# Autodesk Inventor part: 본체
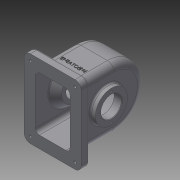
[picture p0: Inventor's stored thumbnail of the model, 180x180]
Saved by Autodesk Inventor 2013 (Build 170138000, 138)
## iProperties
Created: 2016-10
Part Number: 본체
Material: Generic
Document SubType Name: Modeling
Designer: Administrator
Density: 1 g/cm^3
Author: Administrator
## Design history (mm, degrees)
sketch "스케치1"
  geometry: L1 (0, -58)-(-80, -58); L2 (-80, -58)-(-80, 58); L3 (-80, 58)-(0, 58); L4 (0, 58)-(0, -58); L5 (0, -58)-(58, -58); L6 (58, -58)-(58, 58); L7 (58, 58)-(0, 58); L8 (0, 58)-(0, -58); 2 further points
  constraints: 16 end point, 4 parallel, 2 horizontal, 2 perpendicular, 1 coincident, 1 midpoint
  dimensions: "d0" = 116 distance of L3.end L1.start; "d2" = 80 distance of L2.end L3.end; "d3" = 116 distance of L5.end L6.end; "d4" = 58 distance of L6.end L7.end
extrude "돌출1" new body sketch "스케치1" stored distance "d5" = 77; taper "d6" = 0 deg
fillet "모깎기1" dims "d7" = 58
sketch "스케치2"
  geometry: L1 (-38.5, -80)-(-38.5, 58) reference; L2 (-38.5, 58)-(38.5, 58) reference; L3 (38.5, 58)-(38.5, -80) reference; L4 (38.5, -80)-(-38.5, -80) reference; L5 (-33.5, 52)-(33.5, 52); L6 (33.5, 52)-(33.5, 0); L7 (33.5, 0)-(-33.5, 0); L8 (-33.5, 0)-(-33.5, 52); 2 further points
  constraints: 8 end point, 2 parallel, 1 coincident, 1 horizontal, 1 midpoint, 1 perpendicular
  dimensions: "d8" = 5 distance between parallel lines of L1 L8; "d9" = 52 distance between parallel lines of L7 L5
revolve "회전1" sketch "스케치2" stored, may be unused: angle "d10" = 90 deg
sketch "스케치3"
  geometry: L1 (-38.5, -80)-(-38.5, 58) reference; L2 (-38.5, 58)-(38.5, 58) reference; L3 (38.5, 58)-(38.5, -80) reference; L4 (38.5, -80)-(-38.5, -80) reference; L5 (33.5, -52)-(33.5, 52) reference; L6 (33.5, 52)-(-33.5, 52) reference; L7 (-33.5, 52)-(-33.5, -52) reference; L8 (-33.5, -52)-(33.5, -52) reference; L9 (-33.5, 0)-(33.5, 0); L10 (33.5, 0)-(33.5, -80); L11 (33.5, -80)-(-33.5, -80); L12 (-33.5, -80)-(-33.5, 0); 1 further point
  constraints: 8 end point, 2 parallel, 1 horizontal, 1 midpoint, 1 perpendicular, 1 point on line
  dimensions: "d11" = 5 distance between parallel lines of L3 L10
extrude "돌출2" cut sketch "스케치3" stored distance "d12" = 104; taper "d13" = 0 deg
sketch "스케치4"
  geometry: L1 (72, 6)-(5, 6) reference; L2 (5, 6)-(5, 110) reference; L3 (5, 110)-(72, 110) reference; L4 (72, 110)-(72, 6) reference; L5 (93.5, 133)-(-16.5, 133); L6 (-16.5, 133)-(-16.5, -17); L7 (-16.5, -17)-(93.5, -17); L8 (93.5, -17)-(93.5, 133); L9 (93.5, 133)-(-16.5, -17); L10 (-16.5, 133)-(93.5, -17); 1 further point
  constraints: 12 end point, 2 midpoint, 2 parallel, 1 horizontal, 1 perpendicular
  dimensions: "d14" = 110 distance of L6.end L7.end; "d16" = 150 distance of L7.end L5.start
extrude "돌출3" join sketch "스케치4" distance "d17" = 15; taper "d18" = 0 deg
sketch "스케치5"
  geometry: L1 (-33.5, 52)-(-33.5, -80) reference; L2 (-33.5, -80)-(-55, -80) reference; L3 (-55, -80)-(-55, -65) reference; L4 (-55, -65)-(-38.5, -65) reference; L5 (-38.5, -65)-(-38.5, 58) reference; L6 (-38.5, 58)-(38.5, 58) reference; L7 (38.5, 58)-(38.5, -65) reference; L8 (38.5, -65)-(55, -65) reference; L9 (55, -65)-(55, -80) reference; L10 (55, -80)-(33.5, -80) reference; L11 (33.5, -80)-(33.5, 52) reference; L12 (33.5, 52)-(-33.5, 52) reference; L13 (37.5, -15)-(48.5, -15); L14 (48.5, -15)-(48.5, 16); L15 (48.5, 16)-(37.5, 16); L16 (37.5, 16)-(37.5, -15); L17 (33.5, -15)-(38.5, -15); 1 further point
  constraints: 10 end point, 3 point on line, 2 parallel, 2 perpendicular, 1 horizontal
  dimensions: "d20" = 87 distance between parallel lines of L5 L14; "d21" = 31 distance of L13.end L14.end; "d22" = 11 distance of L14.end L15.end; "d23" = 65 distance between parallel lines of L10 L13
revolve "회전2" sketch "스케치5" stored, may be unused: angle "d24" = 90 deg
sketch "스케치6"
  geometry: L1 (-33.5, 52)-(-33.5, -80) reference; L2 (-33.5, -80)-(-55, -80) reference; L3 (-55, -80)-(-55, -65) reference; L4 (-55, -65)-(-38.5, -65) reference; L5 (-38.5, -65)-(-38.5, 58) reference; L6 (-38.5, 58)-(38.5, 58) reference; L7 (38.5, 58)-(38.5, 16) reference; L8 (38.5, 16)-(48.5, 16) reference; L9 (48.5, 16)-(48.5, -46) reference; L10 (48.5, -46)-(38.5, -46) reference; L11 (38.5, -46)-(38.5, -65) reference; L12 (38.5, -65)-(55, -65) reference; L13 (55, -65)-(55, -80) reference; L14 (55, -80)-(33.5, -80) reference; L15 (33.5, -80)-(33.5, 52) reference; L16 (33.5, 52)-(-33.5, 52) reference; L17 (-43.5, 22.5)-(-36.5, 22.5); L18 (-36.5, 22.5)-(-36.5, -15); L19 (-36.5, -15)-(-43.5, -15); L20 (-43.5, -15)-(-43.5, 22.5); 1 further point
  constraints: 8 end point, 2 parallel, 1 horizontal, 1 perpendicular
  dimensions: "d25" = 65 distance between parallel lines of L2 L19; "d26" = 37.5 distance of L19.end L17.start; "d27" = 5 distance between parallel lines of L5 L20; "d28" = 7 distance of L17.start L17.end
revolve "회전3" sketch "스케치6" stored, may be unused: angle "d29" = 90 deg
sketch "스케치7"
  geometry: L1 (-33.5, 52)-(-33.5, -80) reference; L2 (-33.5, -80)-(-55, -80) reference; L3 (-55, -80)-(-55, -65) reference; L4 (-55, -65)-(-38.5, -65) reference; L5 (-38.5, -65)-(-38.5, -52.5) reference; L6 (-38.5, -52.5)-(-43.5, -52.5) reference; L7 (-43.5, -52.5)-(-43.5, 22.5) reference; L8 (-43.5, 22.5)-(-38.5, 22.5) reference; L9 (-38.5, 22.5)-(-38.5, 58) reference; L10 (-38.5, 58)-(38.5, 58) reference; L11 (38.5, 58)-(38.5, 16) reference; L12 (38.5, 16)-(48.5, 16) reference; L13 (48.5, 16)-(48.5, -46) reference; L14 (48.5, -46)-(38.5, -46) reference; L15 (38.5, -46)-(38.5, -65) reference; L16 (38.5, -65)-(55, -65) reference; L17 (55, -65)-(55, -80) reference; L18 (55, -80)-(33.5, -80) reference; L19 (33.5, -80)-(33.5, 52) reference; L20 (33.5, 52)-(-33.5, 52) reference; L21 (-43.5, -15)-(48.5, -15); L22 (-33.5, 13)-(-19.5, 13); L23 (-19.5, 13)-(-19.5, -15); L24 (-19.5, 13)-(-33.5, 24.747); L25 (-33.5, 24.747)-(-33.5, -15); L26 (-33.5, -15)-(-19.5, -15); 1 further point
  constraints: 12 end point, 5 point on line, 2 midpoint, 2 parallel
  dimensions: "d31" = 65 distance between parallel lines of L2 L21; "d32" = 28 distance between parallel lines of L21 L22; "d34" = 50 deg angle of L23 L24; "d35" = 24 distance between parallel lines of L7 L23
revolve "회전4" sketch "스케치7" stored, may be unused: angle "d36" = 90 deg
sketch "스케치8"
  geometry: C1 r 31 at (0, 0) reference; C2 r 20 at (0, 0); 1 further point
  constraints: 1 centre point, 1 coincident
  dimensions: "d37" = 40 diameter of C2
extrude "돌출4" cut sketch "스케치8" stored distance "d38" = 15; taper "d39" = 0 deg
chamfer "모따기1" distance "d40" = 1; stored, may be unused: second distance "d41" = 2, angle "d42" = 45 deg
sketch "스케치9"
  geometry: L1 (48.5, 6)-(47.5, 5) reference; L2 (47.5, 5)-(33.5, 5) reference; L3 (33.5, 5)-(33.5, 52) reference; L4 (33.5, 52)-(-33.5, 52) reference; L5 (-33.5, 52)-(-33.5, 24.747) reference; L6 (-33.5, 24.747)-(-19.5, 13) reference; L7 (-19.5, 13)-(-19.5, 5) reference; L8 (-19.5, 5)-(-42.5, 5) reference; L9 (-42.5, 5)-(-43.5, 6) reference; L10 (-43.5, 6)-(-43.5, 22.5) reference; L11 (-43.5, 22.5)-(-38.5, 22.5) reference; L12 (-38.5, 22.5)-(-38.5, 58) reference; L13 (-38.5, 58)-(38.5, 58) reference; L14 (38.5, 58)-(38.5, 16) reference; L15 (38.5, 16)-(48.5, 16) reference; L16 (48.5, 16)-(48.5, 6) reference; L17 (-55, -65)-(-38.5, -65) reference; L18 (-38.5, -65)-(-38.5, -52.5) reference; L19 (-38.5, -52.5)-(-43.5, -52.5) reference; L20 (-43.5, -52.5)-(-43.5, -36) reference; L21 (-43.5, -36)-(-42.5, -35) reference; L22 (-42.5, -35)-(-19.5, -35) reference; L23 (-19.5, -35)-(-19.5, -43) reference; L24 (-19.5, -43)-(-33.5, -54.747) reference; L25 (-33.5, -54.747)-(-33.5, -80) reference; L26 (-33.5, -80)-(-55, -80) reference; L27 (-55, -80)-(-55, -65) reference; L28 (38.5, -65)-(55, -65) reference; L29 (55, -65)-(55, -80) reference; L30 (55, -80)-(33.5, -80) reference; L31 (33.5, -80)-(33.5, -35) reference; L32 (33.5, -35)-(47.5, -35) reference; L33 (47.5, -35)-(48.5, -36) reference; L34 (48.5, -36)-(48.5, -46) reference; L35 (48.5, -46)-(38.5, -46) reference; L36 (38.5, -46)-(38.5, -65) reference; L37 (-6, 64)-(0, 64); L38 (0, 64)-(0, 55); L39 (-6, 55)-(-6, 64); L40 (-7.587, 55)-(0, 55); L41 (-6, 64)-(-7.587, 55); 1 further point
  constraints: 10 end point, 2 perpendicular, 1 horizontal, 1 parallel, 1 point on line
  dimensions: "d43" = 33.5 distance between parallel lines of L5 L38; "d44" = 144 distance between parallel lines of L26 L37; "d45" = 6 distance of L37.start L37.end; "d46" = 100 deg angle of L13 L41; "d47" = 9 distance between parallel lines of L37 L40
revolve "회전5" sketch "스케치9" stored, may be unused: angle "d48" = 90 deg
sketch "스케치10" dims "d49" = 58
  geometry: C1 r 21 at (0, 0) reference; 3 further points
  constraints: 1 coincident, 1 vertical alignment, 2 other
  dimensions: "d72" = 14 distance of point (0, 15) point (0, 29)
hole "구멍1" sketch "스케치10" at (0, 29) diameter "d50" = 2.459; stored, may be unused: countersink angle "d54" = 90 deg, drill point angle "d56" = 118 deg; dims "d51" = 6, "d52" = 4, "d53" = 2, "d55" = 8
sketch "스케치11" dims "d60" = 52
  geometry: C1 r 21 at (0, 0) reference; 3 further points
  constraints: 1 coincident, 1 vertical alignment, 2 other
  dimensions: "d61" = 11 distance of point (0, 15) point (0, 26)
hole "구멍2" sketch "스케치11" at (0, 26) diameter "d62" = 2.459; stored, may be unused: countersink angle "d66" = 90 deg, drill point angle "d68" = 118 deg; dims "d63" = 6, "d64" = 4, "d65" = 2, "d67" = 8
fillet "모깎기2" dims "d73" = 13
fillet "모깎기3" dims "d74" = 8
fillet "모깎기4" dims "d75" = 12
sketch "스케치12"
  geometry: C1 r 6 at (0, 0) reference; 1 further point
  constraints: 1 coincident
hole "구멍3" sketch "스케치12" at (0, 0) diameter "d76" = 4.459; stored, may be unused: countersink angle "d80" = 90 deg, drill point angle "d82" = 118 deg; dims "d77" = 6, "d78" = 4, "d79" = 2, "d81" = 15
sketch "스케치13"
  geometry: C1 r 6 at (-4.5, 5); C2 r 6 at (81.5, 5); C3 r 6 at (81.5, -121); C4 r 6 at (-4.5, -121); A1 r 12 centre (81.5, 5) between (93.5, 5) and (81.5, 17) reference; A2 r 12 centre (-4.5, 5) between (-4.5, 17) and (-16.5, 5) reference; A3 r 12 centre (-4.5, -121) between (-16.5, -121) and (-4.5, -133) reference; A4 r 12 centre (81.5, -121) between (81.5, -133) and (93.5, -121) reference; 1 further point
  constraints: 4 centre point, 4 coincident
  dimensions: "d83" = 12 diameter of C1; "d84" = 12 diameter of C2; "d85" = 12 diameter of C3; "d86" = 12 diameter of C4
extrude "돌출5" cut sketch "스케치13" distance "d87" = 5; taper "d88" = 0 deg
sketch "스케치14"
  geometry: C1 r 2.5 at (-4.5, 5); C2 r 2.5 at (81.5, 5); C3 r 2.5 at (81.5, -121); C4 r 2.5 at (-4.5, -121); A1 r 12 centre (81.5, 5) between (93.5, 5) and (81.5, 17) reference; A2 r 12 centre (-4.5, 5) between (-4.5, 17) and (-16.5, 5) reference; A3 r 12 centre (-4.5, -121) between (-16.5, -121) and (-4.5, -133) reference; A4 r 12 centre (81.5, -121) between (81.5, -133) and (93.5, -121) reference; 1 further point
  constraints: 4 centre point, 4 coincident
  dimensions: "d89" = 5 diameter of C1; "d90" = 5 diameter of C2; "d91" = 5 diameter of C3; "d92" = 5 diameter of C4
extrude "돌출6" cut sketch "스케치14" stored distance "d93" = 5; taper "d94" = 0 deg
fillet "모깎기5" dims "d95" = 3
fillet "모깎기6" dims "d96" = 3
fillet "모깎기7" dims "d97" = 3
fillet "모깎기8" dims "d98" = 3
sketch "스케치15"
  geometry: L1 (-17.5, -80)-(-29.5, -80) reference; L2 (-13, 0)-(-13, -62) reference; 2 further points
  constraints: 1 other
  dimensions: "d99" = 40 distance from line of L1 point (25.5, -40); "d100" = 38.5 distance from line of point (25.5, -40) L2
feature "엠보싱1" sketch "스케치15" dims "d0" = 116, "d2" = 80, "d3" = 116, "d4" = 58, "d101" = 0.5, "d102" = 0
node "솔리드1"
pattern_circular "원형 패턴1" dims angle "d58" = 360 deg
pattern_circular "원형 패턴2" dims angle "d70" = 360 deg
node "절단 모서리 투영1"
node "절단 모서리 투영2"
node "절단 모서리 투영3"
node "절단 모서리 투영4"
node "절단 모서리 투영5"
node "절단 모서리 투영6"
other parameters: "d19" = 65
